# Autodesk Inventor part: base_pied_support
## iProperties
Shininess: 64.0
Length Units: 11269
Angle Units: 11279
Time Units: 11290
Mass Units: 11283
Length Display Precision: 3
Angle Display Precision: 2
Compacted: True
Part Number: base_pied_support
Document SubType Name: Modeling
Created: 2008-03
Material: Par défaut
Designer: Pascal
Density: 0.0
Volumn: 0.0
Area: 0.0
PropertySet Name: Model Information
Control State: 0
Master: False
Checked Out: False
DESIGNATION: pièce
Author: Pascal
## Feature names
1. Extrusion1
2. Extrusion2
